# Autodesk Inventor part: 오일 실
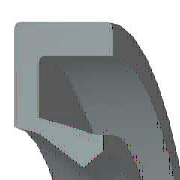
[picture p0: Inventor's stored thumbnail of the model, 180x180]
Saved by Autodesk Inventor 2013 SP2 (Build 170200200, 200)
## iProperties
IsCustomPart: 1
Created: 2012-02
Part Number: 오일 실
Material: 고무
Description: 오일 실 - 스프링 장착, 비스프링, 고무 덮개 G
Document SubType Name: Modeling
Standard: JIS B 2402
Designer: mduedu
Standards Organization: JIS
Language: ko-KR
Size Designation: 20 32 5 A
Categories: <MemberInstance><Categories><Category DisplayName="샤프트 부품" InternalName="7f7aeb1f-a693-4053-b835-cee3144e0d98" Mnemonic="SHFT"><Category DisplayName="실링" Intern
Density: 0.93 g/cm^3
Author: mduedu
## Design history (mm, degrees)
body "Solid1"
revolve "회전1" stored, may be unused: angle "d29" = 360 deg
chamfer "모따기1" distance "d30" = 0.25 (= 0.05 x b); stored, may be unused: second distance "d31" = 0.5 (= 0.1 x b), angle "d39" = 45 deg
chamfer "모따기2" distance "d32" = 0.5 (= 0.1 x b); stored, may be unused: second distance "d33" = 0.25 (= 0.05 x b), angle "d40" = 45 deg
fillet "모깎기1" dims "d34" = 0.25 (= 0.05 x b)
sketch "스케치2"
  geometry: L1 (10.997, -3.438)-(11.297, -5); L2 (10.597, -3.282)-(10.997, -3.438); L3 (10, -1.72)-(10.597, -3.282); L4 (11.091, -1.22)-(10, -1.72); L5 (12.133, -3.75)-(11.091, -1.22); L6 (13.333, -3.75)-(12.133, -3.75); L7 (14.667, -1.25)-(13.333, -3.75); L8 (14.667, 0)-(14.667, -1.25); L9 (16, 0)-(14.667, 0); L10 (16, -5)-(16, 0); L11 (11.297, -5)-(16, -5); L12 (0, -9.6)-(0, 1.6) reference; L13 (28, 0)-(14, 0) reference
  constraints: 22 end point, 3 horizontal, 2 vertical
  dimensions: "d2" = 5 distance of L10.start L9.start (= b); "d4" = 1.25 vertical distance of L5.start L1.end (= 0.25 x b); "d6" = 1.33333 distance of L9.start L8.start (= 0.111111 x dd - 0.111111 x Diam); "d8" = 1.25 distance of L8.start L7.start (= 0.25 x b); "d10" = 1.33333 horizontal distance of L7.start L6.start (= 0.111111 x dd - 0.111111 x Diam); "d12" = 1.21951 vertical distance of L9.start L4.start (= 0.243902 x b); "d14" = 1.09091 horizontal distance of L4.start L3.start (= 0.0909091 x dd - 0.0909091 x Diam); "d16" = 0.5 vertical distance of L4.start L3.start (= 0.1 x b); "d18" = 1.2 distance of L6.start L5.start (= 0.1 x dd - 0.1 x Diam); "d20" = 1.5625 vertical distance of L3.start L2.start (= 0.3125 x b); "d22" = 0.59701 horizontal distance of L3.start L2.start (= 0.0497512 x dd - 0.0497512 x Diam); "d24" = 0.3 horizontal distance of L1.start L1.end (= 0.025 x dd - 0.025 x Diam); "d26" = 1.5625 vertical distance of L1.start L1.end (= 0.3125 x b); "d28" = 0.4 horizontal distance of L2.start L1.start (= 0.0333333 x dd - 0.0333333 x Diam); "d35" = 0 distance between parallel lines of L13 L9; "d36" = 16 distance between parallel lines of L12 L10 (= 0.5 x dd); "d37" = 10 distance from line of L12 L3.start (= 0.5 x Diam)
other parameters: "dd" = 32 [user parameter; used in 8 equation terms], "b" = 5 [user parameter; used in 12 equation terms], "d1" = 8 (derived), "d3" = 2 (derived), "d5" = 2.22222 (derived), "d7" = 2 (derived), "d9" = 2.22222 (derived), "d11" = 1.95122 (derived), "d13" = 1.81818 (derived), "d15" = 0.8 (derived), "d17" = 2 (derived), "d19" = 2.5 (derived), "d21" = 0.99502 (derived), "d23" = 0.5 (derived), "d25" = 2.5 (derived), "d27" = 0.66667 (derived), "d38" = 0
